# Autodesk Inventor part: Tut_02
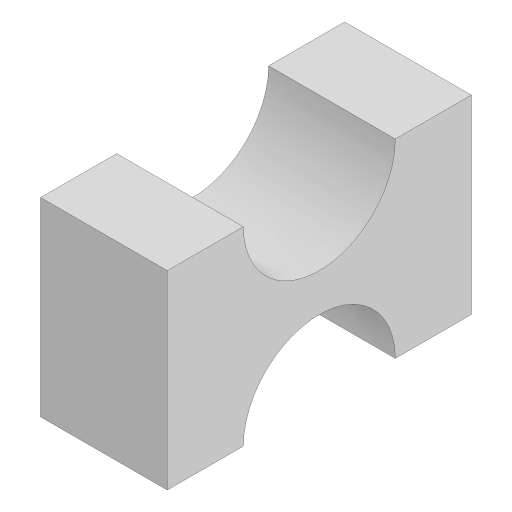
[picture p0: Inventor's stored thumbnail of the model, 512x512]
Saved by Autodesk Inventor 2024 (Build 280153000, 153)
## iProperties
Created: 2022-07
Part Number: Tut_02
Material: Generic
Document SubType Name: Modeling
Designer: LENOVO-CADCIM
Density: 1 g/cm^3
Appearance: Default
Author: LENOVO-CADCIM
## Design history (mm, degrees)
sketch "Sketch5"
  geometry: L1 (0, 0)-(0, 12); L2 (0, 0)-(12, 0); L3 (0, 0)-(0, -12); L4 (0, 12)-(0, 24); L5 (0, 12)-(12, 12); L6 (0, 24)-(-30, 24); L7 (-30, 24)-(-30, 12); L8 (-30, 12)-(-30, -12); L9 (-30, 12)-(-6, 12); L10 (-30, -12)-(-30, -24); L11 (-30, -12)-(-18, -12); L12 (-30, -24)-(0, -24); L13 (0, -24)-(0, -12); L14 (0, -24)-(12, -24); A1 r 12 centre (0, 0) between (0, 12) and (0, -12); A2 r 12 centre (-30, 0) between (-30, -12) and (-30, 12); 1 further point
  constraints: 28 end point, 8 perpendicular, 5 horizontal, 4 point on circle, 2 centre point, 2 vertical, 1 coincident
  dimensions: "d0" = 12 radius of A1; "d1" = 90 deg angle of L2 L1; "d2" = 180 deg angle of L3 L1; "d3" = 12 distance of L1.end L4.end; "d4" = 90 deg angle of L5 L4 (derived); "d5" = 30 distance of L4.end L6.end; "d6" = 90 deg angle of L6 L4 (derived); "d7" = 12 distance of L6.end L7.end; "d8" = 90 deg angle of L7 L6 (derived); "d9" = 24 distance of L7.end L8.end; "d10" = 90 deg angle of L8 L9; "d11" = 12 radius of A2; "d12" = 12 distance of L8.end L10.end; "d13" = 90 deg angle of L10 L11 (derived); "d14" = 30 distance of L10.end L12.end; "d15" = 90 deg angle of L12 L10 (derived); "d16" = 12 distance of L12.end L3.end (derived); "d17" = 90 deg angle of L14 L13 (derived)
extrude "Extrusion1" new body sketch "Sketch5" distance "d18" = 20; taper "d19" = 0 deg
body "Solid1"
